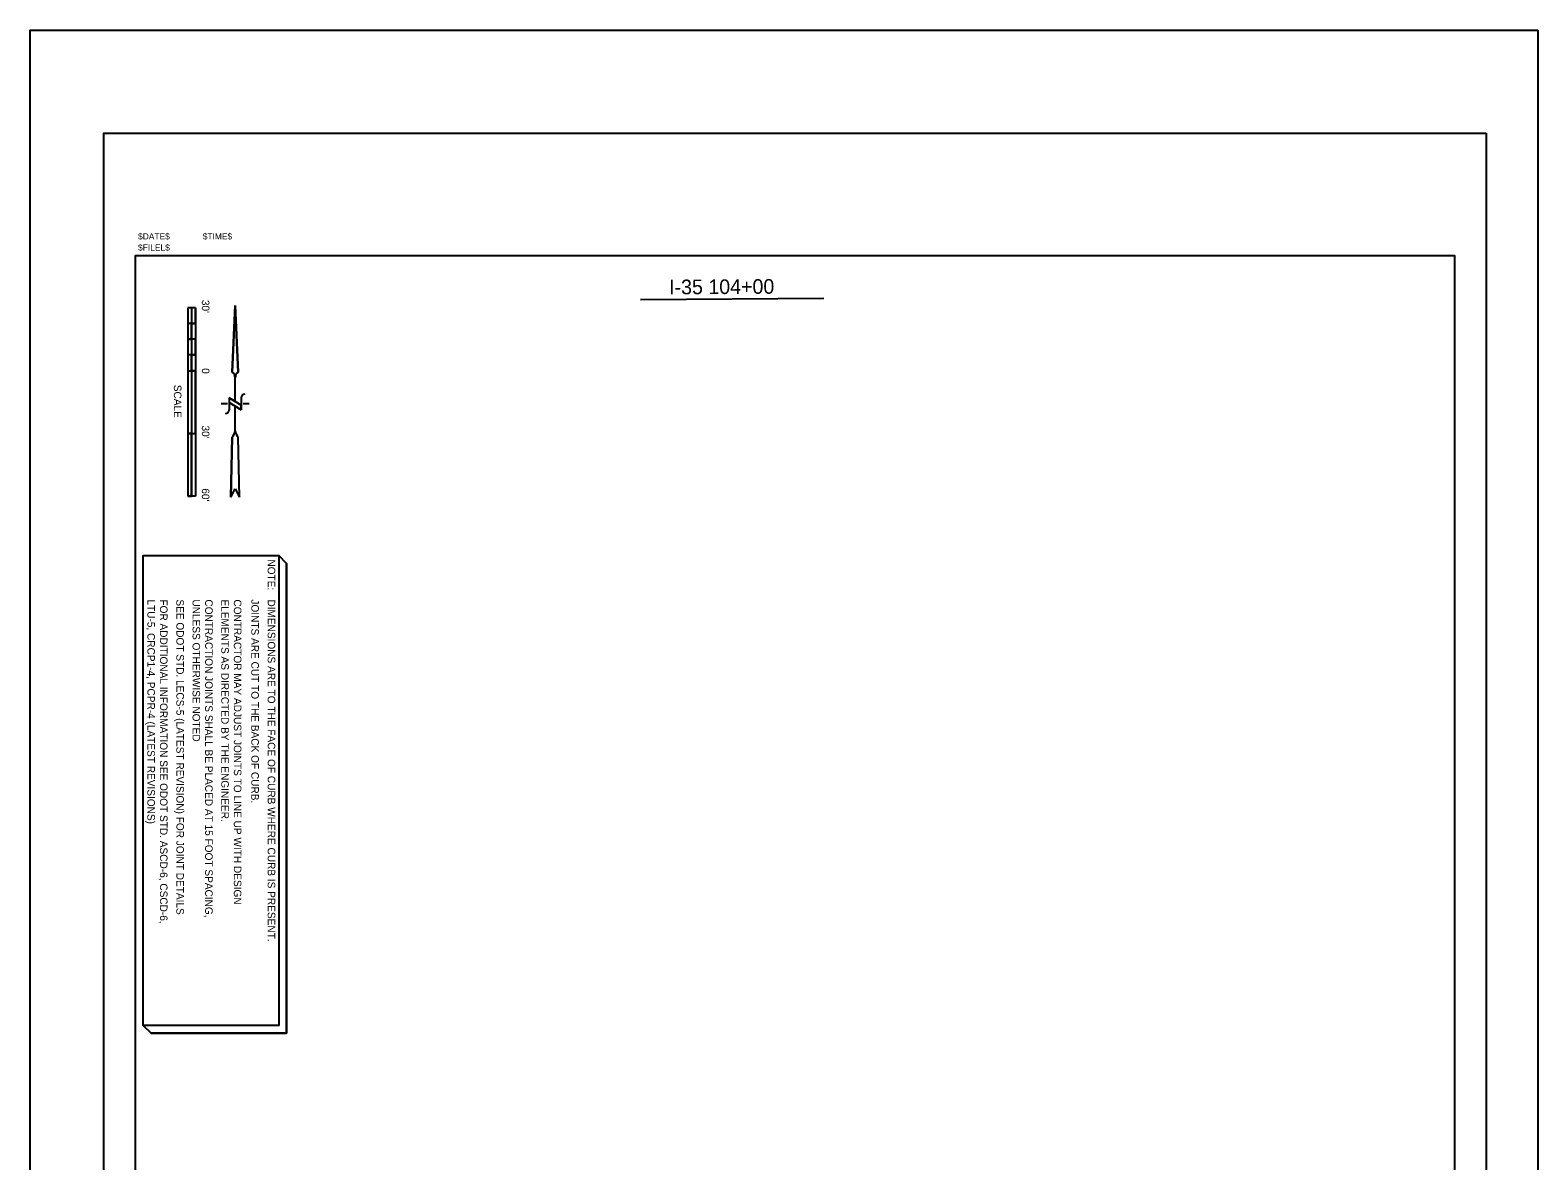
# Model space of a CAD drawing. Extents: x 2150474 to 2151194, y 144668 to 145748.
# Drawn here: x 2150474 to 2151194, y 145208 to 145748 of the extents above; entities that cross this region are included whole.
import ezdxf

# ---------------------------------------------------------------- set-up
doc = ezdxf.new("R2010")
doc.units = 0
for name, color, linetype in [('PR_Shading_1', 7, 'Continuous'), ('PR_Txt', 7, 'Continuous'), ('SHT_Match_Lines', 7, 'Continuous'), ('SHT_North_Arrow', 7, 'Continuous'), ('SHT_Plot_Shape_Full', 7, 'Continuous'), ('SHT_Plot_Shape_Half', 7, 'Continuous'), ('SHT_Plot_Stamp', 7, 'Continuous'), ('SHT_Scale', 7, 'Continuous'), ('SHT_Sheet_Border', 7, 'Continuous')]:
    doc.layers.add(name, color=color, linetype=linetype)

msp = doc.modelspace()

# ---------------------------------------------------------------- linework, layer by layer
at = {"layer": 'PR_Shading_1'}
msp.add_line((2150596.09, 145492.99), (2150592.34, 145496.74), dxfattribs=at)
for points in [[(2150592.34, 145496.74), (2150592.34, 145272.32), (2150527.66, 145272.32)], [(2150527.66, 145272.32), (2150531.41, 145268.57), (2150596.09, 145268.57), (2150596.09, 145492.99)]]:
    msp.add_lwpolyline(points, dxfattribs=at)
at = {"layer": 'PR_Txt'}
msp.add_lwpolyline([(2150592.34, 145496.74), (2150592.34, 145272.32), (2150527.66, 145272.32), (2150527.66, 145496.74)], close=True, dxfattribs=at)
msp.add_lwpolyline([(2150592.34, 145496.74), (2150596.09, 145492.99), (2150596.09, 145268.57), (2150531.41, 145268.57), (2150527.66, 145272.32)], dxfattribs=at)
at = {"layer": 'SHT_Match_Lines'}
msp.add_line((2150852.72, 145619.43), (2150765.12, 145618.9), dxfattribs=at)
at = {"layer": 'SHT_North_Arrow'}
for p, q in [((2150570.1, 145584.36), (2150571.54, 145616.09)), ((2150571.54, 145616.09), (2150570.1, 145584.36)), ((2150571.54, 145616.09), (2150572.98, 145584.36)), ((2150572.98, 145584.36), (2150571.54, 145616.09)), ((2150571.54, 145570.32), (2150571.54, 145581.55)), ((2150574.42, 145568.6), (2150568.66, 145572.05)), ((2150568.66, 145572.05), (2150574.42, 145568.6)), ((2150568.66, 145572.05), (2150568.66, 145566.29)), ((2150571.54, 145570.32), (2150568.66, 145572.05)), ((2150568.66, 145572.05), (2150568.66, 145569.75)), ((2150574.42, 145566.29), (2150568.66, 145569.75)), ((2150574.42, 145568.6), (2150571.54, 145570.32)), ((2150574.42, 145572.05), (2150574.42, 145566.29)), ((2150567.8, 145569.17), (2150564.92, 145569.17)), ((2150571.54, 145556.22), (2150571.54, 145568.02)), ((2150574.42, 145566.29), (2150574.42, 145568.6)), ((2150578.16, 145569.17), (2150575.28, 145569.17)), ((2150569.53, 145524.56), (2150570.1, 145553.34)), ((2150570.1, 145553.34), (2150569.53, 145524.56)), ((2150573.56, 145524.56), (2150572.98, 145553.34)), ((2150573.56, 145524.56), (2150572.98, 145553.34)), ((2150569.53, 145524.56), (2150571.54, 145528.59)), ((2150569.53, 145524.56), (2150571.54, 145528.59)), ((2150571.54, 145528.59), (2150573.56, 145524.56)), ((2150571.54, 145528.59), (2150573.56, 145524.56))]:
    msp.add_line(p, q, dxfattribs=at)
for points in [[(2150568.66, 145569.75), (2150571.54, 145568.02), (2150574.42, 145566.29)], [(2150571.54, 145556.22), (2150571.54, 145556.22), (2150571.54, 145556.22)]]:
    msp.add_lwpolyline(points, dxfattribs=at)
for centre, radius, start, end in [((2150568.09, 145581.55), 3.45, 360, 54.38016), ((2150568.09, 145581.55), 3.45, 360, 54.38016), ((2150574.99, 145581.55), 3.45, 125.61984, 180), ((2150574.99, 145581.55), 3.45, 125.61984, 180), ((2150576.15, 145572.05), 1.73, 90, 180), ((2150566.93, 145566.29), 1.73, 270, 0), ((2150566.53, 145556.92), 5.06, 314.95671, 352.41889), ((2150566.53, 145556.92), 5.06, 314.95671, 352.059), ((2150576.55, 145556.92), 5.06, 187.58111, 225.04329), ((2150576.55, 145556.92), 5.06, 187.941, 225.04329)]:
    msp.add_arc(centre, radius, start, end, dxfattribs=at)
at = {"layer": 'SHT_Plot_Shape_Full'}
msp.add_lwpolyline([(2151193.63, 145747.65), (2151193.63, 144667.65), (2150473.63, 144667.65), (2150473.63, 145747.65)], close=True, dxfattribs=at)
at = {"layer": 'SHT_Plot_Shape_Half'}
msp.add_lwpolyline([(2151168.88, 145698.52), (2151168.88, 144678.52), (2150508.88, 144678.52), (2150508.88, 145698.52)], close=True, dxfattribs=at)
at = {"layer": 'SHT_Scale'}
for p, q in [((2150552.63, 145615.02), (2150548.88, 145615.02)), ((2150548.88, 145615.02), (2150548.88, 145525.02)), ((2150550.76, 145615.02), (2150550.76, 145607.52)), ((2150552.63, 145615.02), (2150550.76, 145615.02)), ((2150550.76, 145615.02), (2150550.76, 145607.52)), ((2150552.63, 145615.02), (2150552.63, 145525.02)), ((2150552.63, 145607.52), (2150552.63, 145615.02)), ((2150552.63, 145607.52), (2150548.88, 145607.52)), ((2150550.76, 145607.52), (2150548.88, 145607.52)), ((2150548.88, 145607.52), (2150548.88, 145600.02)), ((2150550.76, 145607.52), (2150550.76, 145600.02)), ((2150550.76, 145607.52), (2150552.63, 145607.52)), ((2150550.76, 145600.02), (2150550.76, 145607.52)), ((2150552.63, 145600.02), (2150548.88, 145600.02)), ((2150552.63, 145600.02), (2150548.88, 145600.02)), ((2150548.88, 145600.02), (2150550.76, 145600.02)), ((2150550.76, 145600.02), (2150550.76, 145592.52)), ((2150552.63, 145600.02), (2150550.76, 145600.02)), ((2150550.76, 145600.02), (2150550.76, 145592.52)), ((2150552.63, 145592.52), (2150552.63, 145600.02)), ((2150552.63, 145592.52), (2150548.88, 145592.52)), ((2150550.76, 145592.52), (2150548.88, 145592.52)), ((2150548.88, 145592.52), (2150548.88, 145585.02)), ((2150550.76, 145592.52), (2150550.76, 145585.02)), ((2150550.76, 145592.52), (2150552.63, 145592.52)), ((2150550.76, 145585.02), (2150550.76, 145592.52)), ((2150548.88, 145585.02), (2150550.76, 145585.02)), ((2150548.88, 145585.02), (2150550.76, 145585.02)), ((2150550.76, 145585.02), (2150552.63, 145585.02)), ((2150550.76, 145585.02), (2150550.76, 145525.02)), ((2150552.63, 145585.02), (2150550.76, 145585.02)), ((2150550.76, 145585.02), (2150550.76, 145555.02)), ((2150552.63, 145555.02), (2150552.63, 145585.02)), ((2150548.88, 145555.02), (2150550.76, 145555.02)), ((2150550.76, 145555.02), (2150548.88, 145555.02)), ((2150548.88, 145555.02), (2150548.88, 145525.02)), ((2150550.76, 145555.02), (2150552.63, 145555.02)), ((2150550.76, 145555.02), (2150552.63, 145555.02)), ((2150550.76, 145525.02), (2150550.76, 145555.02)), ((2150550.76, 145525.02), (2150548.88, 145525.02)), ((2150548.88, 145525.02), (2150550.76, 145525.02)), ((2150552.63, 145525.02), (2150550.76, 145525.02))]:
    msp.add_line(p, q, dxfattribs=at)
at = {"layer": 'SHT_Sheet_Border'}
msp.add_lwpolyline([(2150523.88, 144695.02), (2150523.88, 145640.02), (2151153.88, 145640.02), (2151153.88, 144695.02)], close=True, dxfattribs=at)

# ---------------------------------------------------------------- texts
at = {"layer": 'PR_Txt'}
for s, height, rotation, p in [('I-35 104+00', 7, 0.38073, (2150778.79, 145621.45)), ('NOTE:', 3.6, 270, (2150587.08, 145494.89)), ('LTU-5, CRCP1-4, PCPR-4 (LATEST REVISIONS)', 3.6, 270, (2150529.62, 145475.78)), ('FOR ADDITIONAL INFORMATION SEE ODOT STD. ASCD-6, CSCD-6,', 3.6, 270, (2150535.63, 145475.78)), ('SEE ODOT STD. LECS-5 (LATEST REVISION) FOR JOINT DETAILS', 3.6, 270, (2150543.47, 145475.78)), ('UNLESS OTHERWISE NOTED', 3.6, 270, (2150551.19, 145475.78)), ('CONTRACTION JOINTS SHALL BE PLACED AT 15 FOOT SPACING,', 3.6, 270, (2150557.2, 145475.78)), ('ELEMENTS AS DIRECTED BY THE ENGINEER.', 3.6, 270, (2150564.9, 145475.78)), ('CONTRACTOR MAY ADJUST JOINTS TO LINE UP WITH DESIGN', 3.6, 270, (2150570.91, 145475.78)), ('JOINTS ARE CUT TO THE BACK OF CURB.', 3.6, 270, (2150579.25, 145475.78)), ('DIMENSIONS ARE TO THE FACE OF CURB WHERE CURB IS PRESENT.', 3.6, 270, (2150587.08, 145475.78))]:
    msp.add_text(s, height=height, rotation=rotation, dxfattribs=at).set_placement(p)
at = {"layer": 'SHT_Plot_Stamp'}
for s, p in [('$DATE$', (2150525.16, 145647.67)), ('$TIME$', (2150556.05, 145647.67)), ('$FILEL$', (2150525.16, 145642.34))]:
    msp.add_text(s, height=3, rotation=360, dxfattribs=at).set_placement(p)
at = {"layer": 'SHT_Scale'}
for s, p in [("30'", (2150555.63, 145618.84)), ('0', (2150555.63, 145586.21)), ('SCALE', (2150542.28, 145578.28)), ("30'", (2150555.63, 145558.84)), ("60'", (2150555.63, 145528.84))]:
    msp.add_text(s, height=3.6, rotation=270, dxfattribs=at).set_placement(p)

doc.saveas('drawing.dxf')
